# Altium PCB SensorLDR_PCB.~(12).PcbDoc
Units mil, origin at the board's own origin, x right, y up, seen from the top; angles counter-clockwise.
Board outline 6000 x 4000 mil, 2 copper layers (Top Layer, Bottom Layer); 19 components, 11 nets, 54 pads, 0 vias.
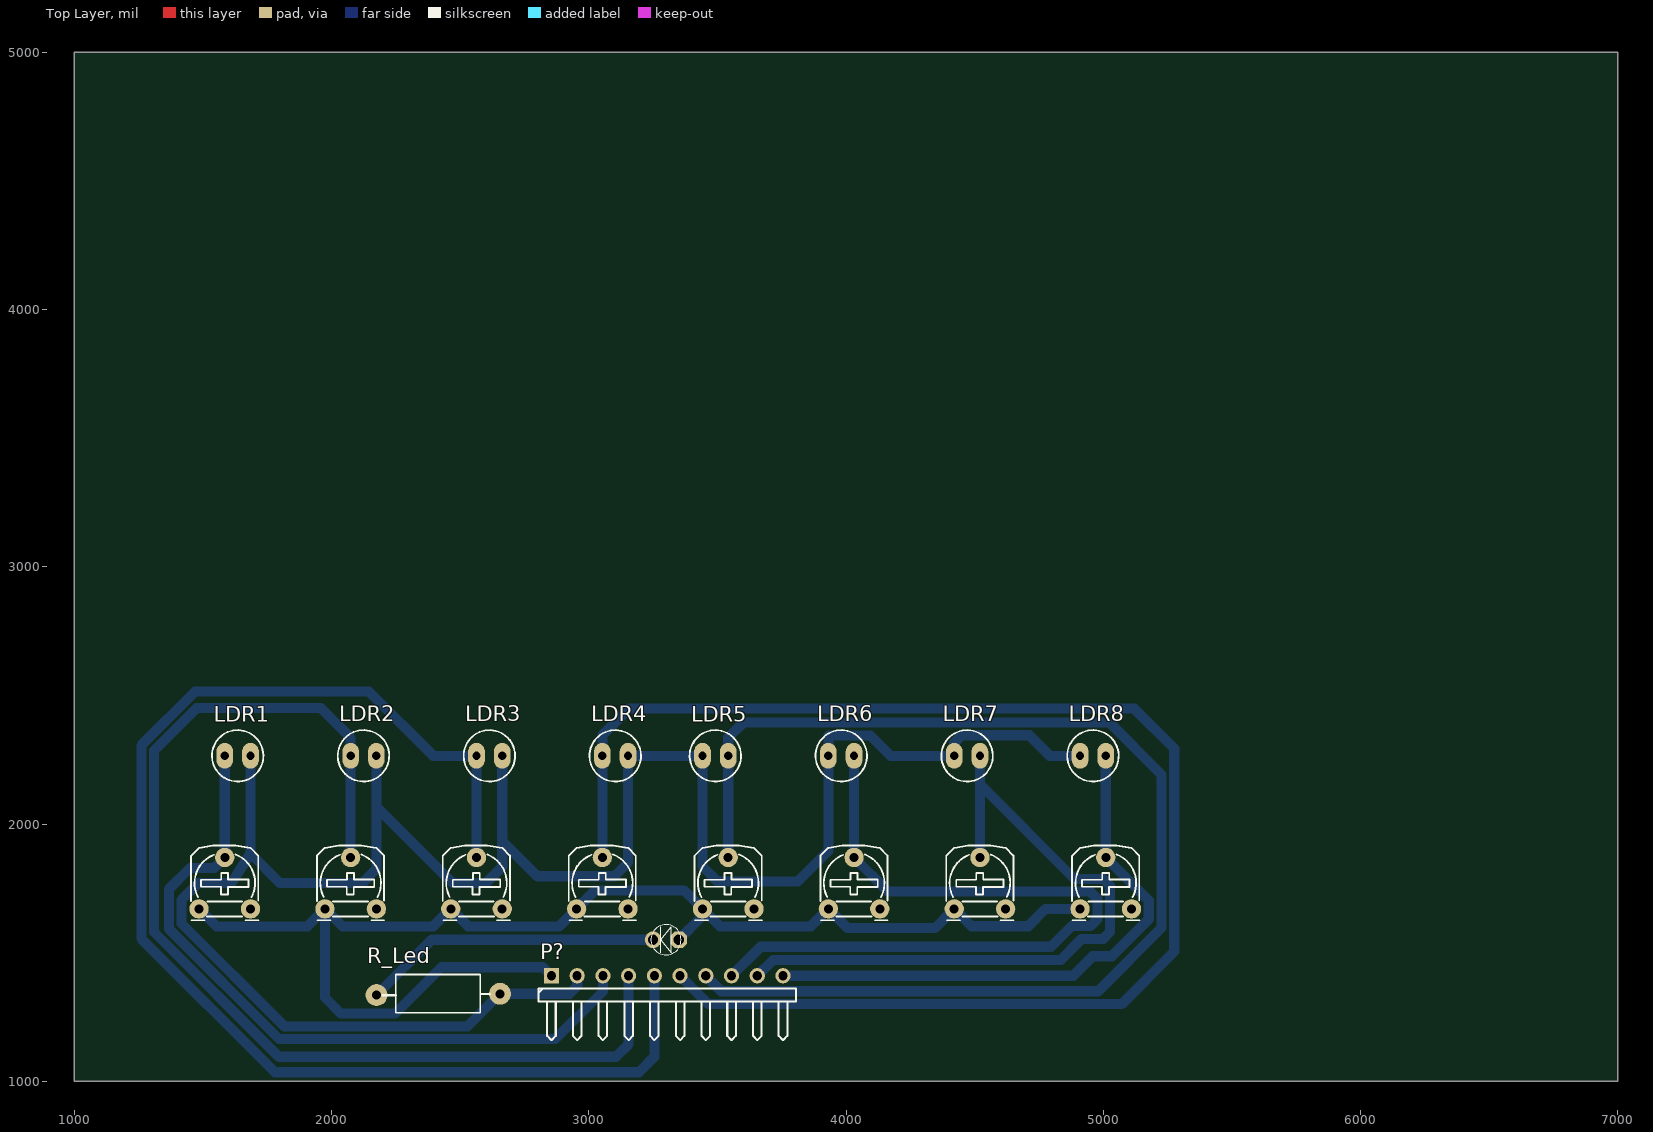
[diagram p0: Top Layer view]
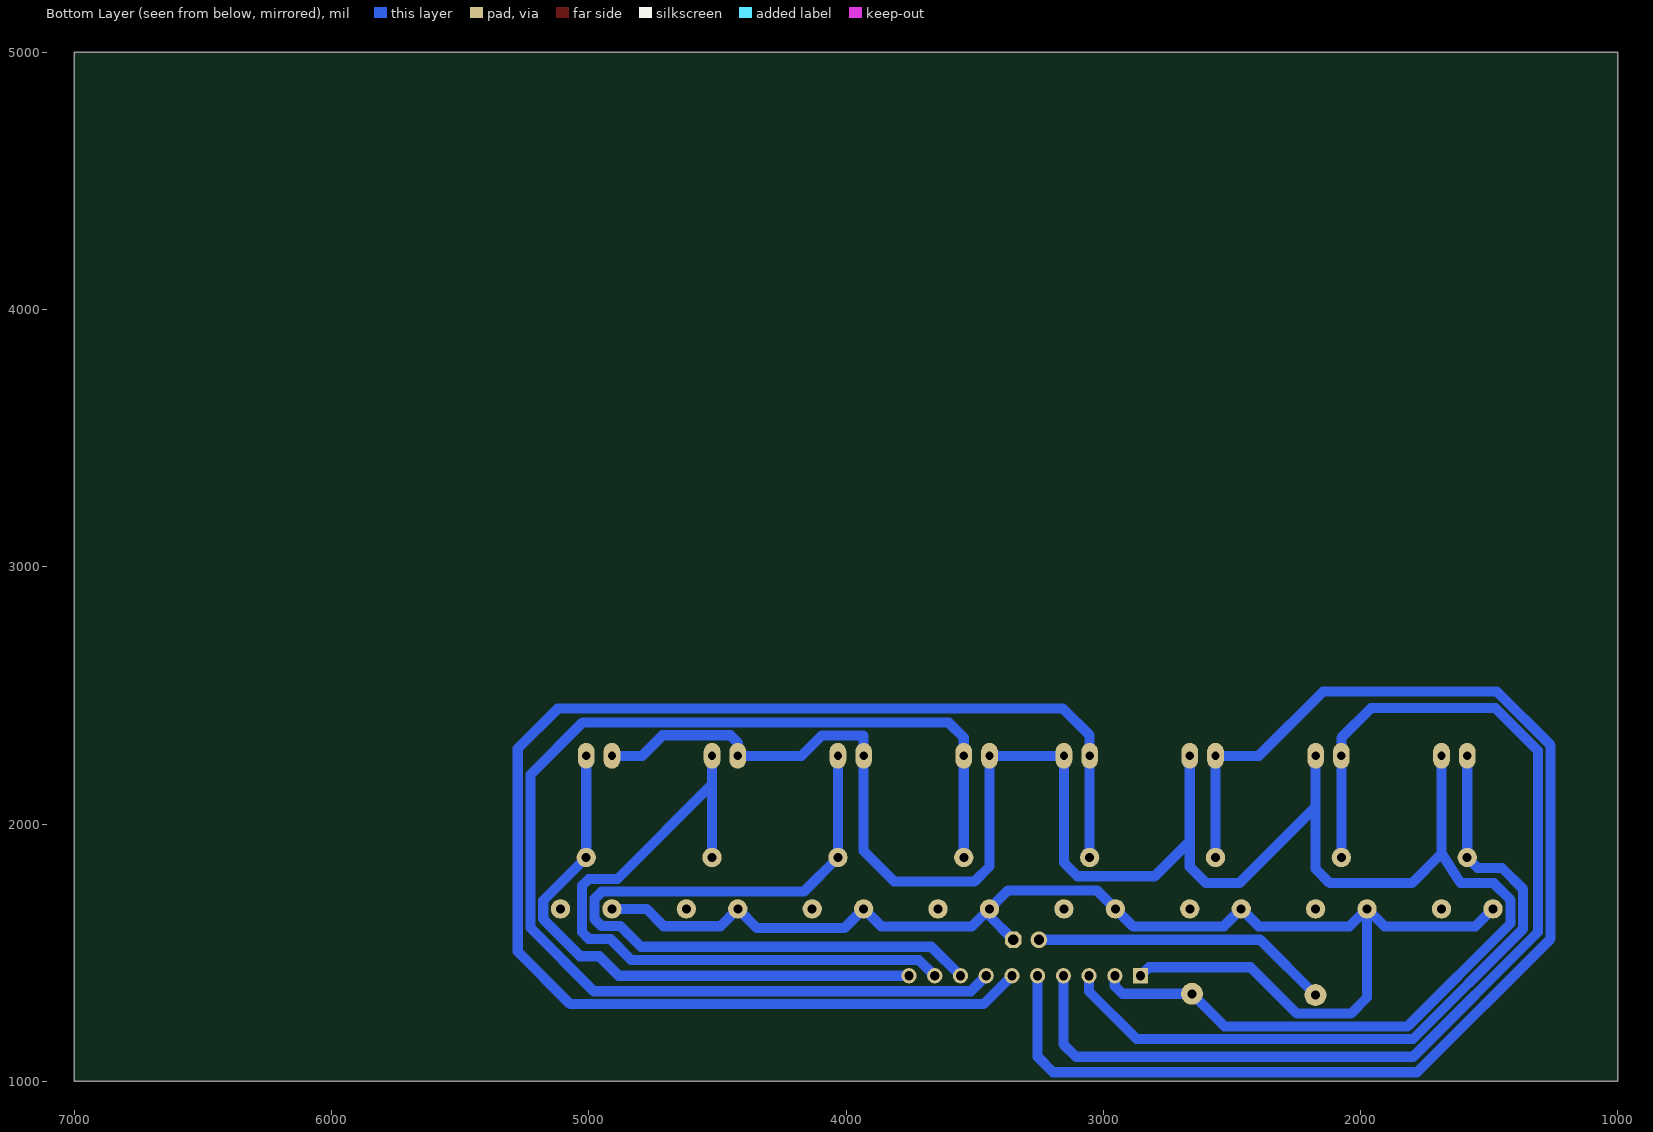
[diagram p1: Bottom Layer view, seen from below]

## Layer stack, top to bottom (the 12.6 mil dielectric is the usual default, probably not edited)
Top Solder: solder mask 0.4, Solder Resist, Dk 3.5
Top Layer: signal copper 1.4
Dielectric 1: dielectric 12.6, FR-4, Dk 4.8
Bottom Layer: signal copper 1.4
Bottom Solder: solder mask 0.4, Solder Resist, Dk 3.5

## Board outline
1000,1000 7000,1000 7000,5000 1000,5000

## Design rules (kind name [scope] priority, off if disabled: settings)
Clearance [All] p1: gap=10 ignorepadtopadclearanceinfootprint=FALSE except(0: Arc-Hole Track-Hole SMDPad-Hole THPad-Hole Via-Hole Fill-Hole Poly-Hole Region-Hole Text-Hole)
PolygonConnect [All] p1: connectstyle=Relief reliefconductorwidth=10 reliefentries=4 polygonreliefangle="90 Angle" airgapwidth=10
RoutingLayers [All] p1: top layer_v5=FALSE bottom layer_v5=TRUE
RoutingVias [All] p1: holewidth=28 width=50 viastyle="Through Hole" minholewidth=28 minwidth=50 maxholewidth=28 maxwidth=50
SolderMaskExpansion [All] p1: expansion=4
Width Others [All] p1: maxlimit=39.37 minlimit=39.37 preferedwidth=39.37
Width VCC [InNet('VCC')] p2: maxlimit=39.37 minlimit=39.37 preferedwidth=39.37
Width GND [InNet('GND')] p3: maxlimit=39.37 minlimit=39.37 preferedwidth=39.37
29 further rules are at their usual default settings.

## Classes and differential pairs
component class SensorLDR: LDR1 LDR2 LDR3 LDR4 LDR5 LDR6 LDR7 LDR8 P? R_Led ""

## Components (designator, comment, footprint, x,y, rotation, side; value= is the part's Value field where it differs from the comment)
LDR1 "LDR" CDS 1685,2265 r180 top
LDR2 "LDR" CDS 2174.29,2265 r180 top
LDR3 "LDR" CDS 2663.57,2265 r180 top
LDR4 "LDR" CDS 3152.86,2265 r180 top
LDR5 "LDR" CDS 3442.14,2265 r0 top
LDR6 "LDR" CDS 3931.43,2265 r0 top
LDR7 "LDR" CDS 4420.71,2265 r0 top
LDR8 "LDR" CDS 4910,2265 r0 top
LED? "LED" LED-3MM-YELLOW 3350,1550 r180 top value="LED 3 ly Single Colour"
P? "Header 10H" HDR1X10H 2855,1410 r0 top
R_Led "Res" RES-1/2W 2395,1340 r0 top
VR1 "50K" VR-S2 1485,1670 r0 top value="Volume 50k"
VR2 "50K" VR-S2 1974.29,1670 r0 top value="Volume 50k"
VR3 "50K" VR-S2 2463.57,1670 r0 top value="Volume 50k"
VR4 "50K" VR-S2 2952.86,1670 r0 top value="Volume 50k"
VR5 "50K" VR-S2 3442.14,1670 r0 top value="Volume 50k"
VR6 "50K" VR-S2 3931.43,1670 r0 top value="Volume 50k"
VR7 "50K" VR-S2 4420.71,1670 r0 top value="Volume 50k"
VR8 "50K" VR-S2 4910,1670 r0 top value="Volume 50k"

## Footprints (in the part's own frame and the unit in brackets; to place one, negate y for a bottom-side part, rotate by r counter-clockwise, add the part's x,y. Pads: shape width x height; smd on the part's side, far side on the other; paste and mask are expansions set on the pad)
CDS [mil] "QUANG TRO"
  oval 65x100 hole 32: 1(0,0) 2(100,0)
  silkscreen extent -50,-100 150,100, body extent -53,-80 153,89, height 138
HDR1X10H [mm] "Connector; Header; 10 Position; Right Angle"
  rect 1.5x1.5 hole 0.9: 1(0,0)
  round 1.5 hole 0.9: 2(2.54,0) 3(5.08,0) 4(7.62,0) 5(10.16,0) 6(12.7,0) 7(15.24,0) 8(17.78,0) 9(20.32,0) 10(22.86,0)
  silkscreen extent -1.27,-6.35 24.13,-1.27
LED-3MM-YELLOW [mil]
  oct 65x65 hole 40: 1(0,0)
  round 65 hole 40: 2(100,0)
  silkscreen extent -9,-59 109,59, body extent -27,-77 117,80, height 181
RES-1/2W [mil]
  round 85 hole 35: 1(-220,-5) 2(260,0)
  silkscreen extent -195,-74 221,75, body extent -230,-60 270,56, height 121
VR-S2 [mil] "Resistor Variable"
  round 75 hole 35: 1(0,0) 2(100,200) 3(200,0)
  silkscreen extent -31,-44 231,246, body extent -87,-30 307,372, height 165

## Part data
LDR1 LDR2 LDR3 LDR4 LDR5 LDR6 LDR7 LDR8: "Quang Tro"
LED?: "LED Single colour Green and Red"
P?: "Header, 10-Pin, Right Angle"
R_Led: Manufacturer="Generic Components"
VR1 VR2 VR3 VR4 VR5 VR6 VR7 VR8: library part VR-S, "Var Resistor"

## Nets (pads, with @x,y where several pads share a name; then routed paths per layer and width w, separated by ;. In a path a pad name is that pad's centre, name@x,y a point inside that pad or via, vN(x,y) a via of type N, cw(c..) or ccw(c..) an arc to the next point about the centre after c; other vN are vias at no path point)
GND: LDR1.1 LDR2.1 LDR3.1 LDR4.1 LDR5.1 LDR6.1 LDR7.1 LDR8.1 P?.2 R_Led.2 | length 8528.6
  Bottom Layer w39.37: LDR1.1 1685,1885 ; LDR2.1 2174.29,2067 ; LDR3.1 2663.57,1933.43 ; P?.2 2955,1370 2925,1340 R_Led.2 2528.44,1213.44 1816.56,1213.44 1417,1613 1417,1705 1482,1770 1610,1770 1685,1885 ; LDR8.1 4792,2265 4712.16,2344.84 4450,2344.84 4420.71,2315.56 LDR7.1 4172.69,2265 4093,2344.69 3931.43,2344.69 LDR6.1 3931.43,1895 3813.43,1777 3500,1777 3442.14,1834.86 LDR5.1 LDR4.1 3152.86,1849.86 3100,1797 2800,1797 2663.57,1933.43 ; 1685,1885 1800,1770 2119,1770 2174.29,1825.29 2174.29,2067 ; 2174.29,2067 2471.29,1770 2600,1770 2663.57,1833.57 2663.57,1933.43
NetLED?_2: LED?.2 R_Led.1 | length 1164.1
  Bottom Layer w39.37: R_Led.1 2390,1550 LED?.2
S1: LDR1.2 P?.3 VR1.2 | length 2820
  Bottom Layer w39.37: LDR1.2 VR1.2 1544,1829 1450,1829 1367.63,1746.63 1367.63,1592.55 1796.11,1164.07 2870.05,1164.07 3055,1349.03 P?.3
S2: LDR2.2 P?.4 VR2.2 | length 4382.9
  Bottom Layer w39.37: VR2.2 LDR2.2 2074.29,2335 1958.29,2451 1476,2451 1310,2285 1310,1580.36 1795.36,1095 3105.63,1095 3155,1144.37 P?.4
S3: LDR3.2 P?.5 VR3.2 | length 5188.8
  Bottom Layer w39.37: VR3.2 LDR3.2 2395,2265 2145,2515 1470,2515 1260.63,2305.63 1260.63,1554.37 1780,1035 3195,1035 3255,1095 P?.5
S4: LDR4.2 P?.6 VR4.2 | length 5645.9
  Bottom Layer w39.37: VR4.2 LDR4.2 3052.86,2345 3156.28,2448.43 5121.06,2448.43 5275.93,2293.56 5275.93,1504.07 5071.43,1299.58 3465.42,1299.58 P?.6
S5: LDR5.2 P?.7 VR5.2 | length 4752.9
  Bottom Layer w39.37: P?.7 3515,1350 4980.3,1350 5226.56,1596.26 5226.56,2191.44 5023,2395 4052.94,2395 4052,2394.06 3600,2394.06 3542.14,2336.2 LDR5.2 VR5.2
S6: LDR6.2 P?.8 VR6.2 | length 3000.3
  Bottom Layer w39.37: P?.8 3668,1523 4797,1523 4876.81,1602.81 4950,1602.81 4977.19,1630 4977.19,1710 4950,1737.19 4164.24,1737.19 VR6.2 LDR6.2
S7: LDR7.2 P?.9 VR7.2 | length 2686.1
  Bottom Layer w39.37: P?.9 3716.66,1471.66 4834.66,1471.66 4916.44,1553.44 5000,1553.44 5026.56,1580 5026.56,1760 5000,1786.56 4888.44,1786.56 4520.71,2154.29 ; VR7.2 4520.71,2154.29 ; LDR7.2 4520.71,2154.29
S8: LDR8.2 P?.10 VR8.2 | length 2217.6
  Bottom Layer w39.37: P?.10 4883.29,1410 4959,1485.71 5032.89,1485.71 5177.19,1630 5177.19,1702.81 VR8.2 LDR8.2
VCC: LED?.1 P?.1 VR1.1 VR2.1 VR3.1 VR4.1 VR5.1 VR6.1 VR7.1 VR8.1 | length 5325.6
  Bottom Layer w39.37: VR1.1 1553,1602 1906.29,1602 VR2.1 ; P?.1 2822,1443 2427.19,1443 2247,1262.81 2036.9,1262.81 1974.29,1325.43 VR2.1 ; LED?.1 3442.14,1642.14 VR5.1 ; VR8.1 4775.63,1670 4708.29,1602.66 4488.05,1602.66 VR7.1 4345.71,1595 4006.43,1595 VR6.1 3863.43,1602 3510.14,1602 VR5.1 ; VR2.1 2042.29,1602 2395.57,1602 VR3.1 2531.57,1602 2884.86,1602 VR4.1 3024.86,1742 3370.14,1742 VR5.1
pads on no net: VR1.3 VR2.3 VR3.3 VR4.3 VR5.3 VR6.3 VR7.3 VR8.3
